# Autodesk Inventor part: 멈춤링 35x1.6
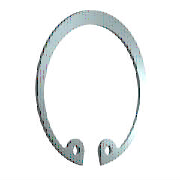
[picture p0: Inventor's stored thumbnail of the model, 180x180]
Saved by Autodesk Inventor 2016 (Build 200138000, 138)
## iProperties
IsCustomPart: 1
Created: 2015-09
Part Number: 멈춤링 35x1.6
Material: 강철, 연강
Description: 리테이닝 링(C형)
Document SubType Name: Modeling
Standard: KS B 1336
Designer: mduedu
Standards Organization: KS
Language: ko-KR
Size Designation: 35x1.6
Categories: <MemberInstance><Categories><Category DisplayName="샤프트 부품" InternalName="7f7aeb1f-a693-4053-b835-cee3144e0d98" Mnemonic="SHFT"><Category DisplayName="써클립" Inter
Density: 7.86 g/cm^3
Mass: 3.5371 g
Surface Area: 9.09651 cm^2
Volume: 0.450013 cm^3
Appearance: 파란색 - 벽 페인트 - 광택
Author: mduedu
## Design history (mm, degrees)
sketch "스케치1"
  geometry: L1 (0, 15.113)-(0, -73.177) reference; L2 (-45.5, 0)-(45.5, 0) reference; L3 (-4.964, 1)-(1.502, 1); L4 (0, -2.5)-(-5.307, -2.5); L5 (0, -17.5)-(-8.583, -33.888); L6 (-8.583, -33.888)-(-21.772, -26.981); L7 (-7.377, -31.585)-(-17.631, -26.214); L8 (-5.162, -32.745)-(-6.29, -34.898); L9 (5.162, -32.745)-(6.29, -34.898); C1 r 1.25 at (-7.377, -31.585); C2 r 1.25 at (7.377, -31.585); A1 r 15.875 centre (0, -18.375) between (11.82, -28.972) and (-11.82, -28.972); A2 r 18.5 centre (0, -17.5) between (6.29, -34.898) and (-6.29, -34.898); A3 r 2.5 centre (-7.377, -31.585) between (-5.162, -32.745) and (-8.668, -29.444); A4 r 2.5 centre (-9.959, -27.303) between (-11.82, -28.972) and (-8.668, -29.444); A5 r 2.5 centre (9.959, -27.303) between (8.668, -29.444) and (11.82, -28.972); A6 r 2.5 centre (7.377, -31.585) between (8.668, -29.444) and (5.162, -32.745); 3 further points
  constraints: 15 point on circle, 14 end point, 9 symmetric about line, 8 centre point, 6 tangent, 4 coincident, 4 point on line, 3 perpendicular, 1 parallel, 4 other
  dimensions: "d8" = 0.875 distance of A1.centre L5.start (= 0.25 x SRB1); "d38" = 3.5 distance between parallel lines of L4 L3 (= SRB1); "d39" = 17.5 distance from line of L5.start L2 (= 0.5 x WD); "d43" = 18.5 radius of A2 (= 0.5 x ND); "d45" = 2.6 distance between parallel lines of L7 L6 (= 0.5 x SRB2); "d46" = 2.5 radius of A4 (= SD5); "d47" = 6.29 distance from line of L1 L8.end (= 0.17 x ND); "d48" = 2.5 diameter of C1 (= SD5); "d49" = 2.5 radius of A3 (= SD5)
extrude "본체" new body sketch "스케치1" distance "d2" = 1.6 (= SD); taper "d3" = 0 deg
workaxis "Work Axis1"
workaxis "Work Axis2"
workplane "Work Plane1"
body "Solid1"
other parameters: "WD" = 35 [user parameter; used in 3 equation terms], "SD" = 1.6 [user parameter; used in 1 equation term], "SRB1" = 3.5 [user parameter; used in 2 equation terms], "ND" = 37 [user parameter; used in 2 equation terms], "SRB2" = 5.2 [user parameter; used in 1 equation term], "SD5" = 2.5 [user parameter; used in 3 equation terms], "d50" = 0, "d51" = 0, "d52" = 0, "d53" = 0, "WDMIN" = 34 [user parameter], "SD6" = 37.8 [user parameter], "WDMAX" = 35 (= WD) [user parameter], "NND" = 35 (= WD) [user parameter]
